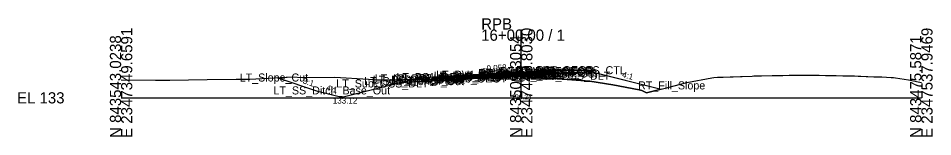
# Model space of a CAD drawing. Extents: x -76 to 2347760, y -10 to 844216.
# Drawn here: x -25.7 to 202.8, y 990.3 to 1019.8 of the extents above; entities that cross this region are included whole.
import ezdxf

# ---------------------------------------------------------------- set-up
doc = ezdxf.new("R2010")
doc.units = 0
for name, color, linetype in [('Default', 7, 'Continuous'), ('Exist Cross Section Cell', 7, 'Continuous'), ('Exist XS Center Line Elevation Label', 7, 'Continuous'), ('Exist XS Ground Line', 7, 'Continuous'), ('Prop CMT Pvmt Course 1', 7, 'Continuous'), ('Prop CMT Pvmt Course 2', 7, 'Continuous'), ('Prop CMT Pvmt Course 3', 7, 'Continuous'), ('Prop CMT Pvmt Surface', 7, 'Continuous'), ('Prop CMT Pvmt Surface Shoulder', 7, 'Continuous'), ('Prop CMT Shld Paved Course 1', 7, 'Continuous'), ('Prop CMT Shld Paved Course 2', 7, 'Continuous'), ('Prop CMT Shld Paved Course 3', 7, 'Continuous'), ('Prop CMT Slope Grass', 7, 'Continuous'), ('Prop CMT Subgrade Earthwork', 7, 'Continuous'), ('Prop XS Ditch Standard Text', 7, 'Continuous'), ('Prop XS Earthwork Shape', 7, 'Continuous'), ('Prop XS SE Text', 7, 'Continuous'), ('Prop XS Side Slope Text', 7, 'Continuous'), ('Scratch_Level_0', 7, 'Continuous')]:
    doc.layers.add(name, color=color, linetype=linetype)

msp = doc.modelspace()

# ---------------------------------------------------------------- linework, layer by layer
at = {"layer": 'Exist Cross Section Cell'}
for p, q in [((100, 1000), (100, 1017.04)), ((0, 1000), (100, 1000)), ((100, 1000), (200, 1000))]:
    msp.add_line(p, q, dxfattribs=at)
at = {"layer": 'Exist XS Ground Line'}
msp.add_lwpolyline([(0, 1004.5), (8.58, 1004.43), (10.92, 1004.43), (12.22, 1004.43), (21.54, 1004.6), (28.77, 1004.69), (32.16, 1004.69), (38.24, 1004.96), (42.78, 1005.24), (45.32, 1005.11), (53.41, 1005.17), (61.87, 1004.65), (64.03, 1004.48), (67.9, 1004.51), (74.65, 1004.66), (78.42, 1004.75), (85.27, 1005.01), (94.97, 1005.38), (95.9, 1005.41), (97.56, 1005.36), (100, 1005.24), (106.52, 1004.91), (111.52, 1004.56), (117.14, 1004.13), (122.89, 1003.28), (129.5, 1001.98), (130.13, 1001.8), (131.32, 1001.23), (136.65, 1002.54), (141.4, 1003.82), (147.6, 1005), (148.14, 1005.11), (149.08, 1005.12), (149.54, 1005.15), (150.51, 1005.18), (152.19, 1005.25), (153, 1005.28), (154.84, 1005.35), (155.23, 1005.36), (157.69, 1005.43), (158.15, 1005.45), (160.09, 1005.5), (162.74, 1005.56), (164.68, 1005.6), (165.42, 1005.61), (166.98, 1005.64), (168.09, 1005.66), (170.1, 1005.67), (170.73, 1005.68), (171.08, 1005.68), (173.36, 1005.64), (174.44, 1005.63), (176.01, 1005.61), (177.5, 1005.58), (178.36, 1005.57), (178.68, 1005.56), (180.34, 1005.53), (181.36, 1005.51), (182.68, 1005.48), (183.26, 1005.45), (184.23, 1005.42), (184.84, 1005.4), (186.17, 1005.36), (186.64, 1005.34), (188.11, 1005.28), (189.29, 1005.24), (190.11, 1005.2), (192.44, 1005.07), (193.01, 1005.07), (193.53, 1004.99), (196.77, 1004.45), (200, 1003.81)], dxfattribs=at)
at = {"layer": 'Prop CMT Pvmt Course 1'}
for p, q in [((100, 1006.44), (88, 1005.75)), ((88, 1005.5), (100, 1006.19)), ((88, 1005.75), (88, 1005.5)), ((100, 1006.44), (104, 1006.67)), ((100, 1006.19), (100, 1006.44)), ((100, 1006.19), (100, 1006.44)), ((104, 1006.42), (100, 1006.19)), ((100, 1006.19), (100, 1006.32)), ((100, 1006.32), (100, 1006.32)), ((100, 1006.32), (100, 1006.19)), ((100, 1006.19), (100, 1006.32)), ((100, 1006.32), (100, 1006.32)), ((100, 1006.32), (100, 1006.19)), ((100, 1006.19), (100, 1006.19)), ((100, 1006.19), (100, 1006.19)), ((104, 1006.67), (104, 1006.42))]:
    msp.add_line(p, q, dxfattribs=at)
at = {"layer": 'Prop CMT Pvmt Course 2'}
for p, q in [((100, 1006.19), (88, 1005.5)), ((88, 1005.16), (100, 1005.86)), ((100, 1006.19), (104, 1006.42)), ((100, 1005.86), (100, 1006.19)), ((100, 1005.86), (100, 1006.19)), ((104, 1006.09), (100, 1005.86)), ((104, 1006.42), (104, 1006.09)), ((88, 1005.5), (88, 1005.16))]:
    msp.add_line(p, q, dxfattribs=at)
at = {"layer": 'Prop CMT Pvmt Course 3'}
for p, q in [((100, 1005.86), (88, 1005.16)), ((100, 1005.86), (104, 1006.09)), ((100, 1005.53), (100, 1005.86)), ((100, 1005.53), (100, 1005.86)), ((104, 1005.76), (100, 1005.53)), ((104, 1006.09), (104, 1005.76)), ((88, 1004.83), (100, 1005.53)), ((88, 1005.16), (88, 1004.83))]:
    msp.add_line(p, q, dxfattribs=at)
at = {"layer": 'Prop CMT Pvmt Surface'}
for q in [(88, 1005.75), (104, 1006.67)]:
    msp.add_line((100, 1006.44), q, dxfattribs=at)
at = {"layer": 'Prop CMT Pvmt Surface Shoulder'}
for p, q in [((88, 1005.75), (78, 1005.17)), ((104, 1006.67), (108, 1006.91))]:
    msp.add_line(p, q, dxfattribs=at)
at = {"layer": 'Prop CMT Shld Paved Course 1'}
for p, q in [((88, 1005.75), (78, 1005.17)), ((88, 1005.5), (88, 1005.75)), ((104, 1006.67), (108, 1006.91)), ((108.24, 1006.67), (104, 1006.42)), ((104, 1006.42), (104, 1006.67)), ((108, 1006.91), (108.24, 1006.67)), ((77.73, 1004.9), (88, 1005.5)), ((78, 1005.17), (77.73, 1004.9))]:
    msp.add_line(p, q, dxfattribs=at)
at = {"layer": 'Prop CMT Shld Paved Course 2'}
for p, q in [((104, 1006.42), (108.24, 1006.67)), ((104, 1006.09), (104, 1006.42)), ((108.55, 1006.35), (104, 1006.09)), ((108.24, 1006.67), (108.55, 1006.35)), ((77.38, 1004.55), (88, 1005.16)), ((77.73, 1004.9), (77.38, 1004.55)), ((88, 1005.5), (77.73, 1004.9)), ((88, 1005.16), (88, 1005.5))]:
    msp.add_line(p, q, dxfattribs=at)
at = {"layer": 'Prop CMT Shld Paved Course 3'}
for p, q in [((104, 1006.09), (108.55, 1006.35)), ((104, 1005.76), (104, 1006.09)), ((109.37, 1006.07), (104, 1005.76)), ((108.55, 1006.35), (109.05, 1006.38)), ((109.05, 1006.38), (109.37, 1006.07)), ((76.53, 1004.17), (88, 1004.83)), ((76.88, 1004.52), (76.53, 1004.17)), ((77.38, 1004.55), (76.88, 1004.52)), ((88, 1005.16), (77.38, 1004.55)), ((88, 1004.83), (88, 1005.16))]:
    msp.add_line(p, q, dxfattribs=at)
at = {"layer": 'Prop CMT Slope Grass'}
for p, q in [((108, 1006.91), (116, 1006.89)), ((116, 1006.89), (135.01, 1002.14)), ((49.19, 1001.62), (39.02, 1005.01)), ((74.14, 1004.86), (55.19, 1000.12)), ((78, 1005.17), (74.14, 1004.86)), ((55.19, 1000.12), (49.19, 1001.62))]:
    msp.add_line(p, q, dxfattribs=at)
at = {"layer": 'Prop CMT Subgrade Earthwork'}
for p, q in [((100, 1005.53), (104, 1005.76)), ((104, 1005.76), (117.42, 1006.54)), ((76.53, 1004.17), (69.81, 1003.78)), ((88, 1004.83), (76.53, 1004.17)), ((100, 1005.53), (88, 1004.83))]:
    msp.add_line(p, q, dxfattribs=at)
at = {"layer": 'Prop XS Earthwork Shape'}
for points in [[(100, 1005.53), (104, 1005.76), (117.42, 1006.54), (135.01, 1002.14), (131.32, 1001.23), (130.13, 1001.8), (129.5, 1001.98), (122.89, 1003.28), (117.14, 1004.13), (111.52, 1004.56), (106.52, 1004.91), (100, 1005.24), (97.56, 1005.36), (97.23, 1005.37)], [(69.81, 1003.78), (55.19, 1000.12), (49.19, 1001.62), (39.02, 1005.01), (42.78, 1005.24), (45.32, 1005.11), (53.41, 1005.17), (61.87, 1004.65), (64.03, 1004.48), (67.9, 1004.51), (73.22, 1004.63)], [(88, 1004.83), (76.53, 1004.17), (69.81, 1003.78), (73.22, 1004.63), (74.65, 1004.66), (78.42, 1004.75), (85.27, 1005.01), (94.97, 1005.38), (95.9, 1005.41), (97.23, 1005.37)]]:
    msp.add_lwpolyline(points, close=True, dxfattribs=at)

# ---------------------------------------------------------------- texts
at = {"layer": 'Default'}
msp.add_text('-', height=0.0001, dxfattribs=at).set_placement((0, 1000))
at = {"layer": 'Exist Cross Section Cell'}
for s, p in [('RPB', (90, 1017.04)), ('16+00.00 / 1', (90, 1014.24)), ('EL 133', (-26, 998.6))]:
    msp.add_text(s, height=2.8, dxfattribs=at).set_placement(p)
for s, p in [('E 2347349.6591', (2.8, 990)), ('E 2347443.8030', (102.8, 990)), ('E 2347537.9469', (202.8, 990)), ('N 843543.0238', (0, 990)), ('N 843509.3054', (100, 990)), ('N 843475.5871', (200, 990))]:
    msp.add_text(s, height=2.8, rotation=90, dxfattribs=at).set_placement(p)
at = {"layer": 'Exist XS Center Line Elevation Label'}
msp.add_text('138.24', height=1.2, dxfattribs=at).set_placement((97.55, 999.64))
at = {"layer": 'Prop XS Ditch Standard Text'}
msp.add_text('133.12', height=1.5, dxfattribs=at).set_placement((52.91, 998.56))
at = {"layer": 'Prop XS SE Text'}
for s, rotation, p in [('0.058', 3.3151, (91.38, 1006.59)), ('4:1', 345.9638, (51.16, 1001.87))]:
    msp.add_text(s, height=1.5, rotation=rotation, dxfattribs=at).set_placement(p)
at = {"layer": 'Prop XS Side Slope Text'}
for s, rotation, p in [('4:1', 345.5351, (125.1, 1005.15)), ('3:1', 341.6601, (45.29, 1003.64)), ('4:1', 14.0362, (63.16, 1002.35))]:
    msp.add_text(s, height=1.5, rotation=rotation, dxfattribs=at).set_placement(p)
at = {"layer": 'Scratch_Level_0'}
for s, p in [('RT_PS1_OEOP', (98.76, 1005.91)), ('RT_GS_OS_CTL', (105.32, 1005.89)), ('LT_Slope_Cut', (29.64, 1004.07)), ('LT_PS3_Shelf_Out', (62.87, 1003.52)), ('LT_GS_OS_CTL', (63.37, 1003.85)), ('LT_PS3_OEOP', (67.62, 1003.55)), ('LT_PS2_OEOP', (67.97, 1003.9)), ('LT_PS1_OEOP', (68.8, 1004.17)), ('LT_Sub_OEOT', (78.08, 1003.83)), ('LT_PV2_OEOT', (78.17, 1004.5)), ('LT_PV3_OEOT', (78.17, 1004.16)), ('LT_PV1_OEOT', (78.74, 1004.75)), ('RT_Sub_OEEOP', (89.17, 1004.53)), ('LT_Sub_OEEOP', (89.21, 1004.53)), ('RT_PV2_OEEOP', (89.26, 1005.19)), ('RT_PV3_OEEOP', (89.26, 1004.86)), ('LT_PV2_OEEOP', (89.31, 1005.19)), ('LT_PV3_OEEOP', (89.31, 1004.86)), ('RT_PV1_OEEOP', (89.83, 1005.32)), ('LT_PV1_OEEOP', (89.87, 1005.32)), ('RT_PV2_IEEOP', (89.91, 1005.19)), ('LT_PV2_IEEOP', (89.95, 1005.19)), ('RT_PV1_IEEOP', (90.47, 1005.32)), ('LT_PV1_IEEOP', (90.52, 1005.32)), ('RT_Sub_Trench_Out', (93.52, 1005.07)), ('PV2_PGL', (93.91, 1005.19)), ('RT_Sub_OEOT', (94.03, 1004.76)), ('RT_PV2_OEOT', (94.13, 1005.42)), ('RT_PV3_OEOT', (94.13, 1005.09)), ('PV1_PGL', (94.47, 1005.44)), ('RT_PV1_OEOT', (94.69, 1005.67)), ('RT_PS3_Shelf_Out', (94.99, 1005.38)), ('RT_PS2_OEOP', (98.43, 1005.67)), ('RT_PS3_OEOP', (98.74, 1005.35)), ('RT_Sub_OSS_DLT', (98.75, 1004.5)), ('LT_Sub_OSS_DLT', (53.78, 1002.58)), ('LT_Sub_Trench_Out', (60.73, 1003.17)), ('RT_Fill_Slope', (129.2, 1002.1)), ('LT_SS_Ditch_Base_Out', (38.08, 1000.85))]:
    msp.add_text(s, height=2, dxfattribs=at).set_placement(p)

doc.saveas('drawing.dxf')
